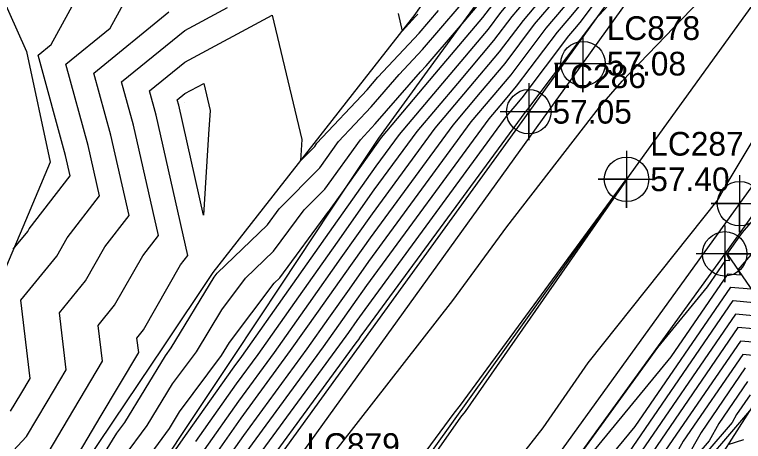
# Model space of a CAD drawing. Extents: x 2188792 to 2191981, y 386090 to 389710.
# Drawn here: x 2189882.1 to 2189959, y 387324.4 to 387369.4 of the extents above; entities that cross this region are included whole.
import ezdxf

# ---------------------------------------------------------------- set-up
doc = ezdxf.new("R2010")
doc.units = 0
for name, color, linetype in [('DTM Contours Major', 7, 'Continuous'), ('DTM Contours Minor', 7, 'Continuous'), ('Exist DTM QL2 LIDAR Elevation Point', 7, 'Continuous'), ('Exist Roads EOP', 7, 'Continuous'), ('Exist Roads EOP Cogo Elevation', 7, 'Continuous'), ('Exist Roads EOP Cogo Number', 7, 'Continuous'), ('Exist Roads EOP Cogo Point CELL', 7, 'Continuous'), ('Exist Roads EOT', 7, 'Continuous'), ('Exist Roads EOT Cogo Elevation', 7, 'Continuous'), ('Exist Roads EOT Cogo Number', 7, 'Continuous'), ('Exist Roads EOT Cogo Point CELL', 7, 'Continuous'), ('PH Exist DTM Breakline', 7, 'Continuous')]:
    doc.layers.add(name, color=color, linetype=linetype)

msp = doc.modelspace()

# ---------------------------------------------------------------- linework, layer by layer
at = {"layer": 'DTM Contours Major'}
for points in [[(2189902.159, 387323.489), (2189905.783, 387328.629), (2189909.53, 387333.744), (2189913.152, 387338.872), (2189916.592, 387343.742), (2189919.864, 387348.374), (2189926.487, 387357.411), (2189930.075, 387361.662), (2189933.277, 387365.455), (2189935.788, 387368.784), (2189938.774, 387372.344), (2189941.464, 387375.552), (2189950.89, 387388.09), (2189953.108, 387391.329), (2189955.309, 387394.543), (2189957.493, 387397.732), (2189959.964, 387401.028)], [(2189960.836, 387388.027), (2189958.804, 387385.627), (2189953.383, 387379.987), (2189945.173, 387370.865), (2189943.367, 387368.884), (2189941.796, 387366.794), (2189941.769, 387366.762), (2189941.739, 387366.727), (2189936.225, 387359.419), (2189936.087, 387359.254), (2189935.931, 387359.07), (2189918.861, 387335.78), (2189918.632, 387335.455), (2189918.391, 387335.114), (2189918.137, 387334.755), (2189907.02, 387319.578)], [(2189882.01, 387344.646), (2189883.527, 387346.524), (2189883.689, 387346.81), (2189888.012, 387352.383), (2189887.525, 387354.536), (2189884.623, 387365.121), (2189885.994, 387366.236), (2189892.349, 387377.889)], [(2189888.784, 387318.515), (2189892.93, 387325.236), (2189893.755, 387326.36), (2189898.064, 387333.412), (2189898.668, 387334.224), (2189903.183, 387341.706), (2189903.492, 387342.115), (2189908.808, 387347.215), (2189910.057, 387348.911), (2189914.313, 387353.242), (2189916.312, 387356.012), (2189919.728, 387359.659), (2189922.692, 387363.06), (2189925.159, 387365.722), (2189929.021, 387370.2)], [(2189899.443, 387359.847), (2189899.291, 387360.399), (2189900.098, 387361.055), (2189902.085, 387362.125), (2189902.756, 387359.291), (2189902.6, 387356.777), (2189902.069, 387348.237), (2189899.443, 387359.847)], [(2189939.829, 387320.314), (2189949.954, 387334.279), (2189955.209, 387340.66), (2189957.144, 387343.48), (2189957.555, 387343.443), (2189957.235, 387344.097), (2189958.882, 387346.421), (2189962.408, 387350.485)], [(2189960.038, 387336.233), (2189958.417, 387336.376), (2189948.894, 387322.496)], [(2189959.689, 387329.273), (2189958.27, 387327.204), (2189957.793, 387326.353), (2189952.262, 387319.899)]]:
    msp.add_lwpolyline(points, dxfattribs=at)
at = {"layer": 'DTM Contours Minor'}
for points in [[(2189893.623, 387322.656), (2189896.111, 387326.046), (2189898.804, 387330.454), (2189901.306, 387333.82), (2189903.984, 387338.258), (2189906.506, 387341.592), (2189909.457, 387344.425), (2189912.669, 387348.783), (2189914.838, 387350.99), (2189918.6, 387356.201), (2189920.149, 387357.855), (2189924.931, 387363.341), (2189925.533, 387363.992), (2189928.945, 387367.947), (2189930.917, 387370.284), (2189931.027, 387370.43), (2189936.377, 387376.809), (2189941.199, 387382.557), (2189943.368, 387385.443), (2189947.565, 387391.571), (2189951.73, 387397.652), (2189955.863, 387403.686), (2189960.537, 387409.923)], [(2189894.316, 387320.075), (2189898.466, 387325.731), (2189899.544, 387327.496), (2189903.945, 387333.416), (2189904.786, 387334.81), (2189909.519, 387341.07), (2189910.107, 387341.634), (2189915.282, 387348.654), (2189915.364, 387348.738), (2189916.342, 387350.092), (2189920.465, 387355.93), (2189920.821, 387356.415), (2189926.468, 387363.106), (2189931.507, 387369.077), (2189932.218, 387370.019), (2189936.977, 387375.693), (2189941.265, 387380.806), (2189945.249, 387386.105), (2189948.951, 387391.511), (2189952.625, 387396.875), (2189956.27, 387402.198), (2189960.394, 387407.699)], [(2189895.121, 387317.827), (2189900.341, 387325.232), (2189905.288, 387332.25), (2189906.087, 387333.34), (2189911.056, 387340.375), (2189915.776, 387347.057), (2189920.265, 387353.411), (2189922.71, 387356.747), (2189927.67, 387362.625), (2189932.097, 387367.87), (2189933.408, 387369.607), (2189937.576, 387374.576), (2189941.332, 387379.054), (2189947.129, 387386.767), (2189950.337, 387391.45), (2189953.519, 387396.097), (2189956.678, 387400.709), (2189960.251, 387405.476)], [(2189901.25, 387324.36), (2189905.535, 387330.44), (2189907.808, 387333.542), (2189912.104, 387339.624), (2189916.184, 387345.4), (2189920.064, 387350.892), (2189924.598, 387357.079), (2189928.873, 387362.143), (2189932.687, 387366.662), (2189934.598, 387369.196), (2189938.175, 387373.46), (2189941.398, 387377.303), (2189949.009, 387387.428), (2189951.722, 387391.389), (2189954.414, 387395.32), (2189957.086, 387399.221), (2189960.107, 387403.252)], [(2189903.068, 387322.617), (2189906.03, 387326.819), (2189911.251, 387333.947), (2189914.2, 387338.121), (2189917, 387342.085), (2189919.663, 387345.855), (2189928.376, 387357.743), (2189931.277, 387361.18), (2189933.866, 387364.248), (2189936.978, 387368.373), (2189939.373, 387371.227), (2189941.531, 387373.8), (2189952.77, 387388.751), (2189954.494, 387391.268), (2189956.204, 387393.765), (2189957.901, 387396.243), (2189959.821, 387398.805)], [(2189959.678, 387396.581), (2189958.309, 387394.755), (2189957.099, 387392.988), (2189955.879, 387391.207), (2189954.65, 387389.413), (2189941.597, 387372.049), (2189939.972, 387370.111), (2189938.169, 387367.961), (2189934.456, 387363.04), (2189932.48, 387360.699), (2189930.265, 387358.074), (2189919.463, 387343.336), (2189917.408, 387340.427), (2189915.247, 387337.369), (2189912.973, 387334.149), (2189906.278, 387325.009), (2189903.978, 387321.746)], [(2189959.534, 387394.357), (2189958.717, 387393.266), (2189957.994, 387392.21), (2189957.265, 387391.147), (2189956.531, 387390.074), (2189941.663, 387370.297), (2189940.571, 387368.995), (2189939.359, 387367.55), (2189935.046, 387361.833), (2189933.682, 387360.217), (2189932.154, 387358.406), (2189919.262, 387340.817), (2189917.816, 387338.77), (2189916.295, 387336.617), (2189914.694, 387334.351), (2189906.525, 387323.199)], [(2189959.124, 387391.777), (2189958.888, 387391.433), (2189958.651, 387391.086), (2189958.411, 387390.736), (2189941.73, 387368.546), (2189941.17, 387367.879), (2189940.549, 387367.138), (2189935.636, 387360.626), (2189934.884, 387359.736), (2189934.042, 387358.738), (2189919.061, 387338.298), (2189918.224, 387337.113), (2189917.343, 387335.866), (2189916.416, 387334.553), (2189906.773, 387321.388)], [(2189914.929, 387322.013), (2189928.336, 387339.246), (2189934.032, 387347.003), (2189943.803, 387359.629), (2189946.193, 387362.388), (2189955.308, 387371.872), (2189966.747, 387385.386)], [(2189881.727, 387327.559), (2189882.794, 387329.354), (2189883.779, 387331.012), (2189882.808, 387339.252), (2189886.582, 387343.925), (2189887.677, 387345.859), (2189891.11, 387350.285), (2189889.908, 387355.599), (2189887.556, 387364.177), (2189892.203, 387367.955), (2189895.76, 387374.478)], [(2189885.105, 387322.219), (2189888.384, 387327.734), (2189891.411, 387332.826), (2189890.967, 387336.591), (2189892.691, 387338.725), (2189895.652, 387343.957), (2189897.307, 387346.09), (2189894.675, 387357.723), (2189893.424, 387362.288), (2189900.098, 387367.714), (2189904.598, 387370.14)], [(2189878.299, 387319.443), (2189883.416, 387324.889), (2189885.589, 387328.544), (2189887.595, 387331.919), (2189886.887, 387337.921), (2189889.636, 387341.325), (2189891.664, 387344.908), (2189894.209, 387348.188), (2189892.292, 387356.661), (2189890.49, 387363.232), (2189898.412, 387369.673)], [(2189886.794, 387319.55), (2189891.178, 387326.924), (2189895.226, 387333.733), (2189895.046, 387335.26), (2189895.745, 387336.125), (2189899.64, 387343.006), (2189900.405, 387343.992), (2189897.059, 387358.785), (2189896.358, 387361.343), (2189900.098, 387364.384), (2189909.308, 387369.349), (2189912.422, 387356.209), (2189912.283, 387353.963), (2189913.787, 387355.495), (2189914.023, 387355.822), (2189919.306, 387361.463), (2189920.453, 387362.778), (2189924.785, 387367.453), (2189926.832, 387369.826)], [(2189922.57, 387369.497), (2189922.992, 387367.652), (2189924.411, 387369.183), (2189924.644, 387369.453)], [(2189965.311, 387365.046), (2189957.256, 387351.588), (2189956.337, 387349.936), (2189942.6, 387332.647), (2189937.835, 387325.802), (2189928.451, 387313.821)], [(2189946.66, 387352.034), (2189946.76, 387352.15), (2189946.685, 387352.015), (2189946.658, 387351.98), (2189929.641, 387327.531), (2189929.168, 387326.928), (2189917.99, 387310.914), (2189917.031, 387309.594), (2189909.085, 387299.587), (2189915.978, 387310.214), (2189916.935, 387311.636), (2189916.971, 387311.69), (2189928.488, 387327.341), (2189929.163, 387328.208), (2189946.641, 387352.009), (2189946.66, 387352.034)], [(2189941.344, 387321.103), (2189951.387, 387333.298), (2189957.398, 387342.059), (2189958.676, 387341.946), (2189958.423, 387342.463), (2189961.388, 387345.881)], [(2189943.247, 387320.692), (2189947.565, 387325.935), (2189957.653, 387340.638), (2189959.797, 387340.449)], [(2189945.143, 387320.613), (2189957.907, 387339.218), (2189960.081, 387339.026)], [(2189960.059, 387337.629), (2189958.162, 387337.797), (2189947.018, 387321.555)], [(2189960.017, 387334.837), (2189958.671, 387334.956), (2189950.769, 387323.438)], [(2189959.995, 387333.441), (2189958.926, 387333.535), (2189952.644, 387324.379), (2189950.534, 387320.618)], [(2189959.18, 387332.114), (2189954.519, 387325.321), (2189952.954, 387322.53)], [(2189959.435, 387330.694), (2189956.394, 387326.262), (2189955.373, 387324.442), (2189951.469, 387319.885)], [(2189959.631, 387327.587), (2189953.055, 387319.912)], [(2189959, 387324.524), (2189957.36, 387324.024)]]:
    msp.add_lwpolyline(points, dxfattribs=at)
at = {"layer": 'Exist DTM QL2 LIDAR Elevation Point'}
msp.add_line((2189900.098, 387360.139), (2189900.098, 387360.139), dxfattribs=at)
at = {"layer": 'Exist Roads EOP'}
for points in [[(2190313.986, 387884.141), (2190285.547, 387843.636), (2190254.588, 387800.045), (2190225.155, 387759.32), (2190194.829, 387717.425), (2190164.291, 387675.101), (2190137.229, 387637.301), (2190105.098, 387592.774), (2190071.411, 387546.221), (2190039.296, 387501.568), (2190007.542, 387457.958), (2189976.844, 387415.407), (2189936.359, 387359.145), (2189907.138, 387318.716), (2189868.636, 387265.243), (2189836.428, 387220.463), (2189805.695, 387177.815), (2189775.592, 387135.957), (2189745.498, 387094.055), (2189715.496, 387052.249), (2189683.869, 387008.07), (2189653.218, 386965.867), (2189623.729, 386924.667)], [(2190335.128, 387868.989), (2190306.373, 387829.271), (2190274.581, 387784.921), (2190245.133, 387744.071), (2190214.553, 387701.741), (2190184.89, 387660.475), (2190157.493, 387622.204), (2190126.048, 387578.501), (2190091.216, 387530.568), (2190059.634, 387486.726), (2190026.932, 387441.783), (2189997.689, 387401.032), (2189957.023, 387344.154), (2189927.908, 387303.922), (2189889.008, 387250.224), (2189856.606, 387205.5), (2189825.68, 387162.612), (2189795.668, 387120.822), (2189765.955, 387079.619), (2189734.998, 387036.704), (2189703.849, 386993.356), (2189673.984, 386951.979), (2189643.253, 386909.427)]]:
    msp.add_lwpolyline(points, dxfattribs=at)
at = {"layer": 'Exist Roads EOP Cogo Point CELL'}
for points in [[(2189936.359, 387362.145), (2189936.359, 387356.145), (2189936.359, 387359.145), (2189939.359, 387359.145), (2189933.359, 387359.145)], [(2189957.023, 387347.154), (2189957.023, 387341.154), (2189957.023, 387344.154), (2189960.023, 387344.154), (2189954.023, 387344.154)]]:
    msp.add_lwpolyline(points, dxfattribs=at)
for centre in [(2189936.359, 387359.145), (2189957.023, 387344.154)]:
    msp.add_circle(centre, 2.344, dxfattribs=at)
at = {"layer": 'Exist Roads EOT'}
for points in [[(2189910.407, 387320.236), (2189942.075, 387364.22), (2189970.438, 387403.768), (2190000.916, 387446.161), (2190032.053, 387489.248), (2190063.107, 387532.142), (2190093.978, 387574.79), (2190125.104, 387617.946), (2190155.102, 387659.638), (2190185.949, 387702.484), (2190216.886, 387745.11), (2190247.602, 387787.3), (2190276.876, 387828.015), (2190303.928, 387865.67), (2190323.039, 387892.195)], [(2190174.375, 387667.889), (2190147.471, 387630.495), (2190115.247, 387585.778), (2190081.202, 387538.232), (2190049.502, 387494.256), (2190017.538, 387450.182), (2189987.334, 387408.357), (2189946.666, 387352.019), (2189917.402, 387311.129), (2189878.955, 387257.772), (2189846.565, 387212.819), (2189815.837, 387170.306), (2189785.374, 387128.351), (2189755.717, 387086.921), (2189724.953, 387044.041), (2189693.727, 387000.805), (2189663.933, 386959.217), (2189633.425, 386917.196)], [(2189989.253, 387391.986), (2189958.581, 387349.453), (2189928.09, 387307.216), (2189909.67, 387281.603), (2189884.44, 387246.513), (2189852.91, 387202.766), (2189821.507, 387159.305), (2189790.01, 387115.85), (2189759.16, 387072.957), (2189728.247, 387029.91), (2189696.407, 386985.689), (2189665.45, 386942.736), (2189635.049, 386900.502)]]:
    msp.add_lwpolyline(points, dxfattribs=at)
at = {"layer": 'Exist Roads EOT Cogo Point CELL'}
for points in [[(2189942.075, 387367.22), (2189942.075, 387361.22), (2189942.075, 387364.22), (2189939.075, 387364.22), (2189945.075, 387364.22)], [(2189946.666, 387355.019), (2189946.666, 387349.019), (2189946.666, 387352.019), (2189943.666, 387352.019), (2189949.666, 387352.019)], [(2189958.581, 387352.453), (2189958.581, 387346.453), (2189958.581, 387349.453), (2189955.581, 387349.453), (2189961.581, 387349.453)]]:
    msp.add_lwpolyline(points, dxfattribs=at)
for centre in [(2189942.075, 387364.22), (2189946.666, 387352.019), (2189958.581, 387349.453)]:
    msp.add_circle(centre, 2.344, dxfattribs=at)
at = {"layer": 'PH Exist DTM Breakline'}
for points in [[(2189887.345, 387318.68), (2189892.587, 387326.516), (2189897.829, 387334.352), (2189903.071, 387342.188), (2189908.394, 387348.992), (2189913.717, 387355.796), (2189919.04, 387362.601), (2189924.363, 387369.405), (2189929.58, 387376.911), (2189936.401, 387386.159), (2189940.535, 387392.152), (2189944.67, 387398.146), (2189949.557, 387405.484), (2189954.444, 387412.823), (2189960.212, 387420.027), (2189965.981, 387427.231), (2189971.527, 387434.519), (2189977.073, 387441.807), (2189982.464, 387449.171), (2189985.78, 387458.197)], [(2189994.327, 387452.545), (2189989.403, 387445.976), (2189984.48, 387439.407), (2189979.557, 387432.838), (2189977.439, 387429.629), (2189975.013, 387427.829), (2189966.069, 387419.239), (2189960.699, 387412.437), (2189955.329, 387405.634), (2189950.593, 387398.64), (2189945.856, 387391.646), (2189941.119, 387384.652), (2189935.964, 387377.579), (2189930.809, 387370.505), (2189925.654, 387363.432), (2189920.499, 387356.359), (2189915.384, 387348.649), (2189910.269, 387340.94), (2189905.154, 387333.231), (2189900.038, 387325.521), (2189894.923, 387317.812)], [(2189840.092, 387450.147), (2189845.027, 387442.632), (2189849.961, 387435.118), (2189854.896, 387427.603), (2189859.239, 387418.762), (2189863.582, 387409.921), (2189867.925, 387401.08), (2189870.621, 387394.702), (2189873.318, 387388.324), (2189876.015, 387381.946), (2189879.705, 387373.731), (2189883.394, 387365.517), (2189885.9, 387353.813), (2189882.998, 387346.975), (2189880.096, 387340.137)], [(2189957.303, 387344.078), (2189960.096, 387340.05), (2189964.956, 387335.144), (2189969.974, 387329.24), (2189976.494, 387322.747)], [(2189964.956, 387335.144), (2189959.912, 387328.028), (2189954.757, 387319.942)]]:
    msp.add_lwpolyline(points, dxfattribs=at)

# ---------------------------------------------------------------- texts
at = {"layer": 'Exist Roads EOP Cogo Elevation'}
msp.add_text('57.05', height=2.5, dxfattribs=at).set_placement((2189938.859, 387357.895))
at = {"layer": 'Exist Roads EOP Cogo Number'}
msp.add_text('LC286', height=2.5, dxfattribs=at).set_placement((2189938.859, 387361.645))
at = {"layer": 'Exist Roads EOT Cogo Elevation'}
for s, p in [('57.08', (2189944.575, 387362.97)), ('57.40', (2189949.166, 387350.769))]:
    msp.add_text(s, height=2.5, dxfattribs=at).set_placement(p)
at = {"layer": 'Exist Roads EOT Cogo Number'}
for s, p in [('LC878', (2189944.575, 387366.72)), ('LC287', (2189949.166, 387354.519)), ('LC879', (2189912.907, 387322.736))]:
    msp.add_text(s, height=2.5, dxfattribs=at).set_placement(p)

doc.saveas('drawing.dxf')
